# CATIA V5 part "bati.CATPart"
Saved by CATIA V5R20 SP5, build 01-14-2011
Part number: bati
Bounding box of the stored display mesh (mm): x -1516.022 to 12435.454, y 0 to 700, z 5717.591 to 13268.487
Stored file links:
  M:\EU_thinkMotion\IAO_2010\iao\IAO_MMS_Groupe1\Problemes\gduval\Gduval\train d'aterrissage squelette + piece kinematic\bati.CATPart
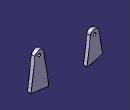
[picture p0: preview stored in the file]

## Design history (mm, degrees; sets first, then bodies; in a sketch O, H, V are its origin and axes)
Body1 (main body)
  Point1: stored without definition
  Sketch1 on zx-plane, origin (0, 0, 0), H (-1, 0, 0), V (0, 0, 1)
    line L1 (-9944.9697, 12517.25) -> (-8965.3437, 6189.9173)
    point P1 (-9944.9697, 12517.25)
    line L2 (-8965.3437, 6189.9173) -> (-12435.4543, 6621.2424)
    line L3 (-12435.4543, 6621.2424) -> (-11697.8085, 12555.7754)
    point P4 (-11697.8085, 12555.7754)
    spline S1 through (-11697.8085, 12555.7754) (-11351.0938, 12998.8125) (-11158.4736, 13133.6504) (-10734.7109, 13268.4873) (-10291.6855, 13095.125) (-9944.9697, 12517.25)
    line L4 (-833.9375, 10629.5254) -> (-1488.8444, 5717.5908)
    point P5 (-833.9375, 10629.5254)
    point P6 (-1488.8444, 5717.5908)
    line L5 (955.9706, 10105.4219) -> (1516.0222, 6488.0898)
    point P7 (955.9706, 10105.4219)
    point P8 (1516.0222, 6488.0898)
    spline S2 through (-833.9375, 10629.5254) (-429.4363, 11265.1875) (533.6621, 11149.6123) (880.3775, 10456.1622) (955.9706, 10105.4219)
    spline S3 through (1516.0222, 6488.0898) (938.1633, 6237.6777) (-1488.8444, 5717.5908)
    point P9 (-11697.8085, 12555.7754)
    point P10 (-9944.9697, 12517.25)
    point P11 (-833.9375, 10629.5254)
    point P12 (955.9706, 10105.4219)
    point P13 (1516.0222, 6488.0898)
    point P14 (-1488.8444, 5717.5908)
    perpendicularity: L3 L2
    coincidence: P9 P4, P10 P1, P11 P5, P12 P7, P13 P8, P14 P6
    parallelism: L5 L1
  Pad1: profile Sketch1, direction (0, 1, 0), length 700
  Point2: stored without definition
  Sketch2 on end face of Pad1, origin (0, 700, 10472.604), H (1, 0, 0), V (0, 0, -1)
    point P1 (0, 0)
    reference projected point E1 (0, 0) from Point1
    coincidence: E1 P1
  Hole1: placed by Sketch2, at (0, 700, 10472.604) direction (0, -1, 0), diameter 520, through (limit type 6)
  Sketch3 on end face of Pad1, origin (10834.35, 700, 12365.631), H (1, 0, 0), V (0, 0, -1)
    point P1 (0, 0)
    reference projected point E1 (0, 0) from Point2
    coincidence: E1 P1
  Hole2: placed by Sketch3, at (10834.35, 700, 12365.631) direction (0, -1, 0), diameter 520, through (limit type 6)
